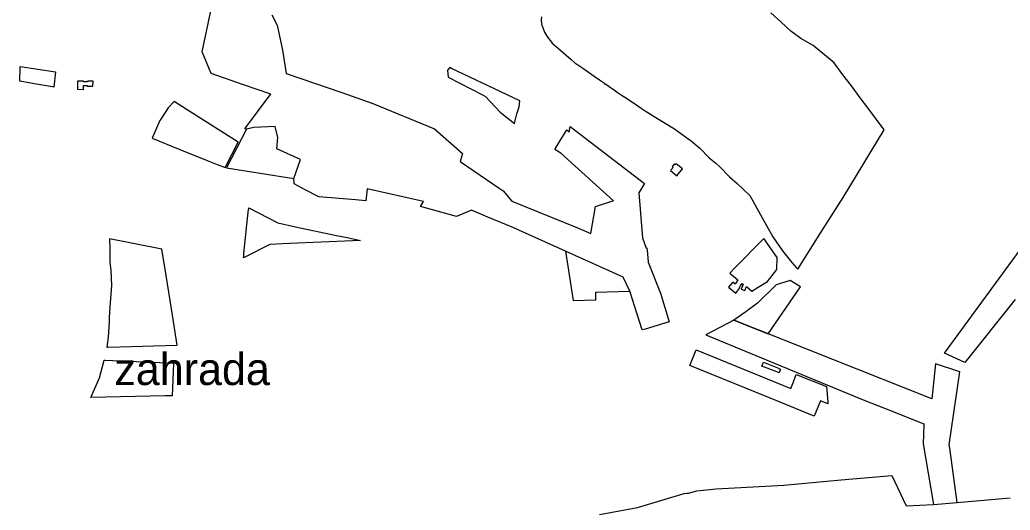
# Model space of a CAD drawing. Extents: x -800505 to -795586, y -1125317 to -1120396.
# Drawn here: x -797996 to -796765, y -1124302 to -1123692 of the extents above; entities that cross this region are included whole.
import ezdxf

# ---------------------------------------------------------------- set-up
doc = ezdxf.new("R2010")
doc.units = 0
for name, color, linetype in [('LES_ZV', 7, 'Continuous'), ('Level 255', 7, 'Continuous'), ('OVNE_PRE', 7, 'Continuous'), ('OVNI_SET', 7, 'Continuous'), ('TRV_POP', 7, 'Continuous'), ('TRV_ZV', 7, 'Continuous')]:
    doc.layers.add(name, color=color, linetype=linetype)

msp = doc.modelspace()

# ---------------------------------------------------------------- linework, layer by layer
at = {"layer": 'LES_ZV'}
for points in [[(-797683, -1123685.7), (-797676.4, -1123698.6), (-797669.8, -1123729.8), (-797665, -1123758.5), (-797595.7, -1123782.4), (-797557.3, -1123796), (-797480.6, -1123827.6), (-797445.8, -1123858.3), (-797448.7, -1123868), (-797400.1, -1123901.3), (-797395.4, -1123904.7), (-797384.4, -1123917.4), (-797303.9, -1123950.3), (-797286.2, -1123957.5), (-797280.7, -1123924.2), (-797260.2, -1123917.5), (-797258.2, -1123916.9), (-797323.6, -1123857.8), (-797330.9, -1123853.2), (-797324.8, -1123842.9), (-797316.3, -1123828.8), (-797313.1, -1123831.5), (-797311.8, -1123824.4), (-797219.5, -1123895.4), (-797226.8, -1123907.3), (-797222.1, -1123963.2), (-797217.4, -1123976.1), (-797216.6, -1123975.7), (-797216.4, -1123978.1), (-797215, -1123993.2), (-797199.7, -1124031.8), (-797188.8, -1124067.6), (-797218.7, -1124076.6), (-797222.7, -1124077.7), (-797238, -1124029.4), (-797246.3, -1124011.9), (-797317.8, -1123979.7), (-797383.9, -1123949.8), (-797414.5, -1123937.2), (-797434.8, -1123928.6), (-797453.4, -1123936.6), (-797498.2, -1123923.9), (-797494.5, -1123918), (-797564.3, -1123902), (-797565.8, -1123916.9), (-797578.8, -1123915.8), (-797624.3, -1123912), (-797641.3, -1123903.2), (-797655.1, -1123896), (-797655.7, -1123889.2), (-797647.3, -1123865.8), (-797676.6, -1123852.3), (-797675.3, -1123838.1), (-797678.8, -1123824.5), (-797705.2, -1123825.7), (-797714.5, -1123827.8), (-797716.4, -1123827.5), (-797685.1, -1123785.3), (-797684.3, -1123784.3), (-797717.9, -1123772.7), (-797758.1, -1123758.8), (-797769.6, -1123731.8), (-797740.2, -1123592.4)], [(-797995.5, -1123749.8), (-797951.7, -1123756.6), (-797953.7, -1123775.6), (-797955.6, -1123775.2), (-797975.4, -1123771.9), (-797978.4, -1123771.5), (-797980.3, -1123771), (-797996.1, -1123768.3), (-797996.1, -1123766.9), (-797995.6, -1123753), (-797995.5, -1123749.8)], [(-797381.2, -1123820.9), (-797380.3, -1123817.1), (-797378.4, -1123808.7), (-797375.3, -1123800.3), (-797374.7, -1123792.8), (-797414.1, -1123774), (-797459.5, -1123752.4), (-797461.4, -1123751.4), (-797464.4, -1123754.7), (-797463.5, -1123763.3), (-797420, -1123785.8), (-797417.2, -1123787.2), (-797399.2, -1123806.7), (-797381.2, -1123820.9)], [(-797711.6, -1123925.6), (-797675.5, -1123944.4), (-797653.4, -1123949.2), (-797602.6, -1123960), (-797589.2, -1123962.8), (-797572.8, -1123966.2), (-797582.1, -1123966.7), (-797661, -1123970.3), (-797685.4, -1123971.4), (-797718.1, -1123988), (-797717.8, -1123985.8), (-797717.5, -1123982.6), (-797712.2, -1123931.2), (-797711.6, -1123925.6)], [(-796759, -1124039.8), (-796821.2, -1124118.1), (-796846.6, -1124106.4), (-796715.4, -1123926.9)], [(-796831, -1124292.1), (-796840.2, -1124224.5), (-796840.7, -1124220.4), (-796835.1, -1124180.9), (-796827.8, -1124129.7), (-796857.9, -1124119.8), (-796862.4, -1124163.5), (-797108.5, -1124065.4), (-797117.4, -1124070.1), (-797143.2, -1124083.8), (-797138.2, -1124085.8), (-796993.1, -1124145.8), (-796947.6, -1124164.6), (-796921.4, -1124174.9), (-796872.3, -1124194.3), (-796872.8, -1124207.6), (-796873.3, -1124219.1), (-796860.5, -1124294.6)]]:
    msp.add_lwpolyline(points, dxfattribs=at)
at = {"layer": 'Level 255'}
for points in [[(-797155.2, -1124102.3), (-797037.7, -1124150.3), (-797034.5, -1124142), (-797031, -1124132.9), (-796993.2, -1124147.9), (-796991.8, -1124167.4), (-796991.8, -1124169.5), (-797000.7, -1124165.8), (-797008.6, -1124185.1), (-797055.3, -1124165.9), (-797163.2, -1124121.8), (-797155.2, -1124102.3)], [(-797071.8, -1124117.9), (-797053.2, -1124125.3), (-797053.2, -1124125.5), (-797050.6, -1124126.6), (-797052.3, -1124130.8), (-797054.9, -1124129.7), (-797055, -1124129.9), (-797073.7, -1124122.5), (-797071.8, -1124117.9)]]:
    msp.add_lwpolyline(points, dxfattribs=at)
at = {"layer": 'OVNE_PRE'}
msp.add_lwpolyline([(-797275.6, -1124307.3), (-797228.3, -1124298.4), (-797170.4, -1124281), (-797167, -1124280.8), (-797164.9, -1124280.7), (-797154.4, -1124277.9), (-797130.7, -1124275.1), (-797046.5, -1124270.6), (-796975.1, -1124264.2), (-796912.3, -1124258.5), (-796894.3, -1124296.5), (-796860.5, -1124294.6), (-796831, -1124292.1), (-796765, -1124286.6)], dxfattribs=at)
at = {"layer": 'OVNI_SET'}
for points in [[(-797347.7, -1123688.1), (-797347.9, -1123692.1), (-797347.5, -1123697.5), (-797346.6, -1123700.8), (-797343.8, -1123707.4), (-797341.4, -1123711.5), (-797338.8, -1123715), (-797336.4, -1123718), (-797334.2, -1123720.8), (-797326.5, -1123727.5), (-797310.8, -1123741.1), (-797306.3, -1123745.5), (-797295, -1123752.9), (-797282.1, -1123761.8), (-797275.6, -1123766.4), (-797269.4, -1123770.8), (-797269.6, -1123771), (-797268.4, -1123771.9), (-797268.2, -1123771.6), (-797261.7, -1123776.1), (-797257.3, -1123779.1), (-797253.6, -1123781.8), (-797246.2, -1123786.7), (-797244.2, -1123788), (-797234.5, -1123794.4), (-797228, -1123799), (-797223.9, -1123801.9), (-797218.6, -1123805.2), (-797205.7, -1123813.3), (-797182.4, -1123827.5), (-797164.2, -1123840.8), (-797163.6, -1123840.7), (-797150.9, -1123851.6), (-797139.2, -1123863.7), (-797131, -1123870.4), (-797126.2, -1123874.4), (-797113.8, -1123887.3), (-797104.6, -1123895.6), (-797088.6, -1123910.3), (-797075.8, -1123933.8), (-797060.2, -1123961.9), (-797048.1, -1123979.2), (-797036.4, -1123993.8), (-797030.5, -1124000.3), (-797028.8, -1124002.1), (-797000.2, -1123956.3), (-796972.8, -1123912.9), (-796921.6, -1123828.9), (-796942.1, -1123801.4), (-796951.5, -1123788.8), (-796961.2, -1123775.8), (-796974.1, -1123758.5), (-796983.9, -1123745.2), (-797010.1, -1123723.9), (-797025.3, -1123715), (-797037.9, -1123706.2), (-797049.8, -1123694.6), (-797062.7, -1123683.2)], [(-797916.8, -1123768.4), (-797924.4, -1123768.2), (-797924.6, -1123778.2), (-797917.1, -1123778.4), (-797917, -1123773.6), (-797912.3, -1123773.7), (-797912.4, -1123774.3), (-797905.4, -1123774.5), (-797905.1, -1123768.1), (-797912.2, -1123768), (-797912.2, -1123769.1), (-797916.8, -1123769), (-797916.8, -1123768.4)], [(-797831.5, -1123838.9), (-797797.2, -1123853), (-797792.9, -1123854.7), (-797763.4, -1123866.8), (-797750.8, -1123872), (-797740.9, -1123875.6), (-797724.8, -1123844), (-797741.7, -1123833.3), (-797788.1, -1123803.7), (-797804.1, -1123793.5), (-797811.9, -1123801.5), (-797820.8, -1123815.3), (-797821.9, -1123817.3), (-797831.5, -1123838.9)], [(-797714.5, -1123827.8), (-797739.1, -1123876.2), (-797655.7, -1123889.2), (-797647.3, -1123865.8), (-797676.6, -1123852.3), (-797675.3, -1123838.1), (-797678.8, -1123824.5), (-797705.2, -1123825.7), (-797714.5, -1123827.8)], [(-797180.2, -1123870.9), (-797181.3, -1123872.2), (-797182.5, -1123871.2), (-797185.1, -1123874.4), (-797183.9, -1123875.4), (-797187.2, -1123879.5), (-797179.5, -1123885.8), (-797172.5, -1123877.3), (-797180.2, -1123870.9)], [(-797884.7, -1123964.3), (-797884.1, -1123976.3), (-797884.3, -1123993.4), (-797882.9, -1124003.4), (-797882.2, -1124022.5), (-797884.2, -1124049.2), (-797885, -1124062.3), (-797885.1, -1124067.8), (-797886.3, -1124086.7), (-797888.1, -1124099.2), (-797886.7, -1124099.1), (-797857.1, -1124098.2), (-797830.1, -1124097.3), (-797800.4, -1124096.4), (-797806.4, -1124059.3), (-797807.7, -1124051.3), (-797814.3, -1124009.9), (-797819.7, -1123977.1), (-797884.7, -1123964.3)], [(-797071.1, -1123964), (-797076.4, -1123969), (-797102.2, -1123995.4), (-797108, -1124001.3), (-797113.5, -1124007.1), (-797103.4, -1124015.4), (-797106.3, -1124019.8)], [(-797100.5, -1124023.3), (-797098, -1124019.7), (-797097, -1124020.6), (-797099.5, -1124027), (-797094.9, -1124028.7), (-797093, -1124023.8), (-797086, -1124029.5), (-797078.3, -1124024.5), (-797066.9, -1124017.2), (-797055.1, -1124002.4), (-797054.5, -1123987.6), (-797071.1, -1123964)], [(-797317.8, -1123979.7), (-797308.1, -1124041.2), (-797279.9, -1124040.3), (-797280.1, -1124030.8), (-797238, -1124029.4), (-797246.3, -1124011.9), (-797317.8, -1123979.7)], [(-797106.3, -1124019.8), (-797106.9, -1124020.6), (-797109.9, -1124018.2), (-797115.3, -1124024.6), (-797105.9, -1124032.1), (-797101.2, -1124025.4), (-797101.7, -1124025), (-797100.5, -1124023.3)], [(-797038.4, -1124016.1), (-797055.9, -1124021.7), (-797079.1, -1124044.4), (-797093.8, -1124055.3), (-797108.5, -1124065.4), (-797065.8, -1124082.4), (-797025.8, -1124023.9), (-797038.4, -1124016.1)]]:
    msp.add_lwpolyline(points, dxfattribs=at)
at = {"layer": 'TRV_ZV'}
msp.add_lwpolyline([(-797891.3, -1124115.1), (-797890, -1124115.2), (-797821.9, -1124118.1), (-797805.1, -1124118.8), (-797806.6, -1124159.5), (-797815.3, -1124159.7), (-797907.8, -1124161.8), (-797897.1, -1124137.4), (-797891.3, -1124115.1)], dxfattribs=at)

# ---------------------------------------------------------------- texts
at = {"layer": 'TRV_POP'}
msp.add_text('zahrada', height=40, dxfattribs=at).set_placement((-797878.6, -1124146.2))

doc.saveas('drawing.dxf')
